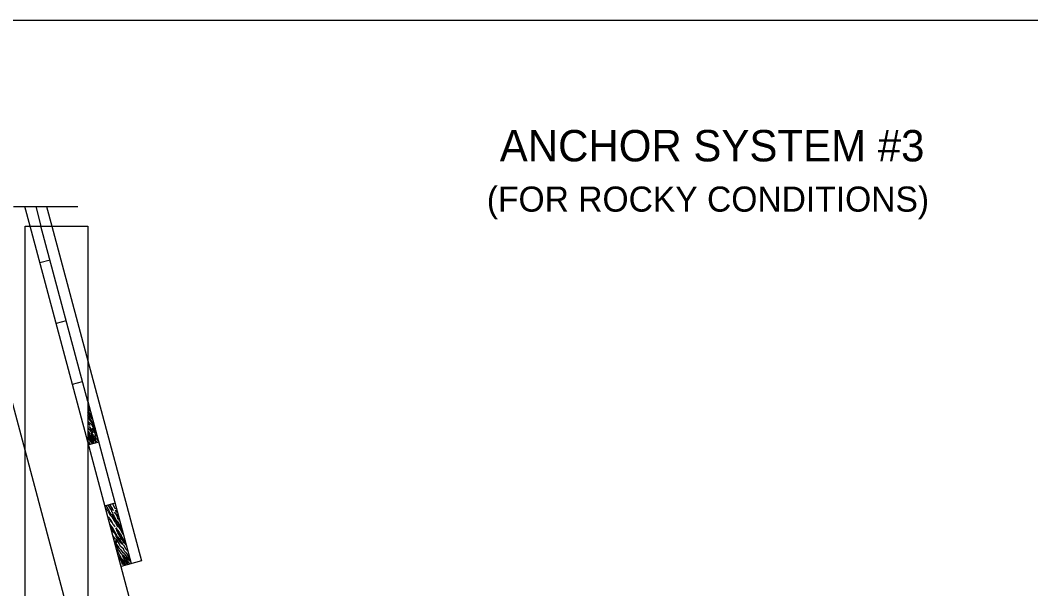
# Model space of a CAD drawing. Extents: x 49991.4 to 50021, y 49987.6 to 50011.4.
# Drawn here: x 50004.937 to 50008.155, y 49997.19 to 49998.999 of the extents above; entities that cross this region are included whole.
import ezdxf

# ---------------------------------------------------------------- set-up
doc = ezdxf.new("R2010")
doc.units = 0
for name, color, linetype in [('Level 1', 7, 'Continuous'), ('Level 2', 7, 'Continuous'), ('Level 4', 7, 'Continuous'), ('Level 6', 7, 'Continuous')]:
    doc.layers.add(name, color=color, linetype=linetype)

msp = doc.modelspace()

# ---------------------------------------------------------------- linework, layer by layer
at = {"layer": 'Level 1'}
for p, q in [((50004.9525, 49997.6307), (50004.7448, 49998.4062)), ((50004.9687, 49998.3434), (50004.9519, 49998.4062)), ((50004.9862, 49998.4062), (50005.0031, 49998.3434)), ((50005.0207, 49998.4062), (50005.0376, 49998.3434)), ((50004.9525, 49995.5838), (50004.9525, 49998.3434)), ((50004.9525, 49998.3434), (50005.1525, 49998.3434)), ((50005.1525, 49998.3434), (50005.1525, 49995.5838)), ((50005.1525, 49997.9147), (50005.3229, 49997.2784)), ((50005.1525, 49997.7858), (50005.2906, 49997.2697)), ((50005.3364, 49996.97), (50005.1525, 49997.6571)), ((50005.1872, 49997.6561), (50005.1551, 49997.6474)), ((50005.2068, 49997.4542), (50005.2389, 49997.4629)), ((50005.3229, 49997.2784), (50005.2585, 49997.261))]:
    msp.add_line(p, q, dxfattribs=at)
msp.add_lwpolyline([(49999.3835, 49998.9992), (50016.7501, 49998.9992), (50016.7501, 49987.7988), (49999.3835, 49987.7988)], close=True, dxfattribs=at)
for points in [[(50005.1525, 49997.7704), (50005.1557, 49997.7506), (50005.1591, 49997.7452), (50005.1619, 49997.7416), (50005.1674, 49997.7301)], [(50005.1525, 49997.7682), (50005.1585, 49997.7569), (50005.1608, 49997.7547)], [(50005.1682, 49997.727), (50005.1615, 49997.7342), (50005.1525, 49997.7504)], [(50005.1716, 49997.7143), (50005.1598, 49997.7291), (50005.1525, 49997.7408)], [(50005.1525, 49997.738), (50005.1601, 49997.7246), (50005.1649, 49997.7182), (50005.1756, 49997.6996)], [(50005.1766, 49997.6958), (50005.1695, 49997.7026), (50005.1655, 49997.7114), (50005.1525, 49997.7227)], [(50005.1602, 49997.7095), (50005.1588, 49997.7115), (50005.1549, 49997.7162), (50005.1567, 49997.7122), (50005.1597, 49997.7095)], [(50005.1574, 49997.7056), (50005.1643, 49997.6934), (50005.1653, 49997.6914), (50005.1671, 49997.6897), (50005.1689, 49997.6858), (50005.1655, 49997.6942), (50005.1635, 49997.6962), (50005.1578, 49997.7057)], [(50005.1525, 49997.7024), (50005.1617, 49997.6899), (50005.1673, 49997.6809), (50005.1714, 49997.6792), (50005.1729, 49997.677)], [(50005.1525, 49997.6782), (50005.1594, 49997.6648), (50005.1627, 49997.6616), (50005.1697, 49997.6514)], [(50005.1661, 49997.6601), (50005.1605, 49997.6706), (50005.1571, 49997.6763), (50005.1554, 49997.6828), (50005.1537, 49997.6856), (50005.1576, 49997.68), (50005.1639, 49997.6724), (50005.1689, 49997.6644), (50005.1713, 49997.6601)], [(50005.1602, 49997.6833), (50005.1588, 49997.6854), (50005.1549, 49997.69), (50005.1567, 49997.6861), (50005.1597, 49997.6833)], [(50005.1785, 49997.6564), (50005.1739, 49997.6628), (50005.169, 49997.6708), (50005.1662, 49997.6747), (50005.1649, 49997.6778), (50005.1624, 49997.6837), (50005.1657, 49997.6781), (50005.169, 49997.6752), (50005.1723, 49997.6724), (50005.1749, 49997.6674), (50005.1769, 49997.6612), (50005.1826, 49997.6549)], [(50005.1826, 49997.6734), (50005.1803, 49997.6762), (50005.1765, 49997.6798), (50005.1755, 49997.6854), (50005.1701, 49997.695), (50005.166, 49997.7007)], [(50005.1672, 49997.7002), (50005.1749, 49997.692), (50005.1789, 49997.6871)], [(50005.1731, 49997.6769), (50005.1771, 49997.6718), (50005.1771, 49997.6702), (50005.1789, 49997.6668), (50005.1809, 49997.6662), (50005.1868, 49997.6577)], [(50005.1525, 49997.6695), (50005.1563, 49997.6677), (50005.1575, 49997.667), (50005.1578, 49997.6649), (50005.1597, 49997.6624), (50005.162, 49997.6592), (50005.1665, 49997.6505)], [(50005.1525, 49997.6662), (50005.1557, 49997.6656), (50005.1595, 49997.6597), (50005.1643, 49997.6541), (50005.1646, 49997.6524), (50005.1651, 49997.6501)], [(50005.1613, 49997.6491), (50005.159, 49997.6524), (50005.1551, 49997.6571), (50005.1569, 49997.6532), (50005.1601, 49997.6488)], [(50005.1736, 49997.6524), (50005.1663, 49997.6656), (50005.1631, 49997.6696), (50005.1626, 49997.6705)], [(50005.1721, 49997.6685), (50005.1705, 49997.6716), (50005.1693, 49997.673)], [(50005.2097, 49997.455), (50005.2157, 49997.4438), (50005.219, 49997.4408), (50005.2203, 49997.4348), (50005.2236, 49997.4323), (50005.2241, 49997.4294), (50005.2251, 49997.4269), (50005.2282, 49997.4258), (50005.2308, 49997.4199), (50005.2385, 49997.4108), (50005.24, 49997.4064), (50005.2461, 49997.3988), (50005.2494, 49997.3914), (50005.2533, 49997.3892), (50005.2543, 49997.3849), (50005.2583, 49997.3787), (50005.263, 49997.3729)], [(50005.216, 49997.4567), (50005.2223, 49997.4466), (50005.2269, 49997.4408), (50005.2275, 49997.436), (50005.2313, 49997.432), (50005.2323, 49997.4258), (50005.2356, 49997.4204), (50005.2385, 49997.4168), (50005.2428, 49997.4078), (50005.2479, 49997.4035), (50005.2533, 49997.3926), (50005.2555, 49997.3906), (50005.2579, 49997.3841), (50005.2607, 49997.3815)], [(50005.2219, 49997.4583), (50005.2287, 49997.4461), (50005.2297, 49997.4441), (50005.2315, 49997.4424), (50005.2333, 49997.4385), (50005.23, 49997.447), (50005.2279, 49997.4489), (50005.2223, 49997.4584)], [(50005.2443, 49997.4428), (50005.2395, 49997.445), (50005.2307, 49997.4606)], [(50005.2088, 49997.4466), (50005.2167, 49997.4365), (50005.2193, 49997.4312), (50005.2226, 49997.4247), (50005.2287, 49997.4182), (50005.2356, 49997.406), (50005.2405, 49997.3996), (50005.2466, 49997.3874), (50005.2499, 49997.3866), (50005.2586, 49997.3745), (50005.2625, 49997.3644), (50005.2651, 49997.365)], [(50005.2163, 49997.4188), (50005.2194, 49997.4173), (50005.2205, 49997.4166), (50005.2209, 49997.4145), (50005.2227, 49997.4119), (50005.2251, 49997.4088), (50005.2295, 49997.4004)], [(50005.2541, 49997.4059), (50005.2517, 49997.4089), (50005.2479, 49997.4126), (50005.2469, 49997.4182), (50005.2415, 49997.4278), (50005.2374, 49997.4334)], [(50005.2451, 49997.4329), (50005.2437, 49997.435), (50005.2399, 49997.4396), (50005.2415, 49997.4357), (50005.2445, 49997.4329)], [(50005.24, 49997.4294), (50005.2476, 49997.4213), (50005.2513, 49997.4164)], [(50005.2184, 49997.4108), (50005.2219, 49997.41), (50005.2257, 49997.4041), (50005.2305, 49997.3986), (50005.2308, 49997.3969), (50005.2325, 49997.396)], [(50005.2456, 49997.3577), (50005.2385, 49997.3706), (50005.233, 49997.3813), (50005.2279, 49997.3886), (50005.2227, 49997.395)], [(50005.2247, 49997.3875), (50005.2307, 49997.3768), (50005.236, 49997.37), (50005.2305, 49997.3798), (50005.2241, 49997.3896)], [(50005.2397, 49997.3872), (50005.2383, 49997.3893), (50005.2345, 49997.3939), (50005.2362, 49997.39), (50005.2392, 49997.3872)], [(50005.228, 49997.3751), (50005.2367, 49997.3663), (50005.242, 49997.3577)], [(50005.2869, 49997.2836), (50005.2769, 49997.3018), (50005.2743, 49997.3046), (50005.2695, 49997.308), (50005.2654, 49997.3165), (50005.2565, 49997.3244), (50005.2521, 49997.334), (50005.2434, 49997.3469), (50005.2391, 49997.3489), (50005.2365, 49997.3534), (50005.2322, 49997.3593)], [(50005.2538, 49997.3577), (50005.2481, 49997.3682), (50005.2447, 49997.3739), (50005.2431, 49997.3804), (50005.2414, 49997.3832), (50005.2453, 49997.3776), (50005.2516, 49997.37), (50005.2565, 49997.362), (50005.259, 49997.3577)], [(50005.2799, 49997.3096), (50005.2731, 49997.3162), (50005.269, 49997.325), (50005.257, 49997.3354), (50005.2416, 49997.3576)], [(50005.2452, 49997.3576), (50005.2531, 49997.3469), (50005.2587, 49997.3379), (50005.2629, 49997.3362), (50005.2644, 49997.334)], [(50005.256, 49997.3577), (50005.2495, 49997.3698), (50005.2463, 49997.3737), (50005.2457, 49997.3746)], [(50005.2749, 49997.3281), (50005.2633, 49997.3427), (50005.2559, 49997.3494), (50005.2559, 49997.3542), (50005.2534, 49997.3576)], [(50005.2556, 49997.3576), (50005.2595, 49997.3526), (50005.2595, 49997.3509), (50005.2613, 49997.3475), (50005.2633, 49997.3469), (50005.2677, 49997.3407), (50005.2725, 49997.3337)], [(50005.2587, 49997.3576), (50005.2626, 49997.3503), (50005.2659, 49997.3472), (50005.2724, 49997.3376)], [(50005.2376, 49997.3392), (50005.2473, 49997.3252), (50005.2513, 49997.3198), (50005.2559, 49997.3145), (50005.2611, 49997.3069), (50005.2685, 49997.3021), (50005.2733, 49997.2945), (50005.2789, 49997.2874), (50005.2893, 49997.2744)], [(50005.2789, 49997.2665), (50005.2731, 49997.2753), (50005.2682, 49997.2835), (50005.2651, 49997.2914), (50005.2644, 49997.2902), (50005.2613, 49997.2987), (50005.2575, 49997.3018), (50005.2555, 49997.3078), (50005.2513, 49997.3128), (50005.2475, 49997.3165), (50005.2465, 49997.3221), (50005.2383, 49997.3367)], [(50005.2447, 49997.3368), (50005.2433, 49997.3389), (50005.2395, 49997.3435), (50005.2412, 49997.3396), (50005.2442, 49997.3368)], [(50005.2445, 49997.3135), (50005.2529, 49997.2965), (50005.2552, 49997.2945), (50005.2575, 49997.288), (50005.2644, 49997.2818), (50005.2687, 49997.2711), (50005.2728, 49997.2683), (50005.2748, 49997.2654)], [(50005.2495, 49997.2949), (50005.2529, 49997.2931), (50005.2539, 49997.2888), (50005.258, 49997.2826), (50005.2629, 49997.2764), (50005.2626, 49997.2742), (50005.2646, 49997.2714), (50005.2701, 49997.2641)], [(50005.2514, 49997.2876), (50005.2583, 49997.2784), (50005.2621, 49997.2683), (50005.2646, 49997.2688), (50005.2689, 49997.2638)], [(50005.282, 49997.27), (50005.2774, 49997.2764), (50005.2725, 49997.2844), (50005.2697, 49997.2883), (50005.2685, 49997.2914), (50005.2659, 49997.2973), (50005.2692, 49997.2917), (50005.2725, 49997.2888), (50005.2759, 49997.286), (50005.2784, 49997.281), (50005.2805, 49997.2748), (50005.2861, 49997.2685)], [(50005.2756, 49997.2821), (50005.2741, 49997.2852), (50005.2728, 49997.2866)]]:
    msp.add_lwpolyline(points, dxfattribs=at)
at = {"layer": 'Level 4'}
for p, q in [((50005.1525, 49997.6571), (50004.9687, 49998.3434)), ((50005.1525, 49997.7858), (50005.0031, 49998.3434)), ((50005.0376, 49998.3434), (50005.1525, 49997.9147)), ((50005.032, 49998.2357), (50004.9999, 49998.227)), ((50005.0837, 49998.0425), (50005.0516, 49998.0338)), ((50005.1034, 49997.8406), (50005.1355, 49997.8493)), ((50005.1525, 49996.8838), (50004.9525, 49997.6307))]:
    msp.add_line(p, q, dxfattribs=at)
at = {"layer": 'Level 6'}
msp.add_line((50004.9152, 49998.4062), (50005.1207, 49998.4062), dxfattribs=at)

# ---------------------------------------------------------------- texts
at = {"layer": 'Level 2'}
for s, height, p in [('ANCHOR SYSTEM #3', 0.1, (50006.4642, 49998.5499)), ('(FOR ROCKY CONDITIONS)', 0.08, (50006.4229, 49998.3899))]:
    msp.add_text(s, height=height, dxfattribs=at).set_placement(p)

doc.saveas('drawing.dxf')
